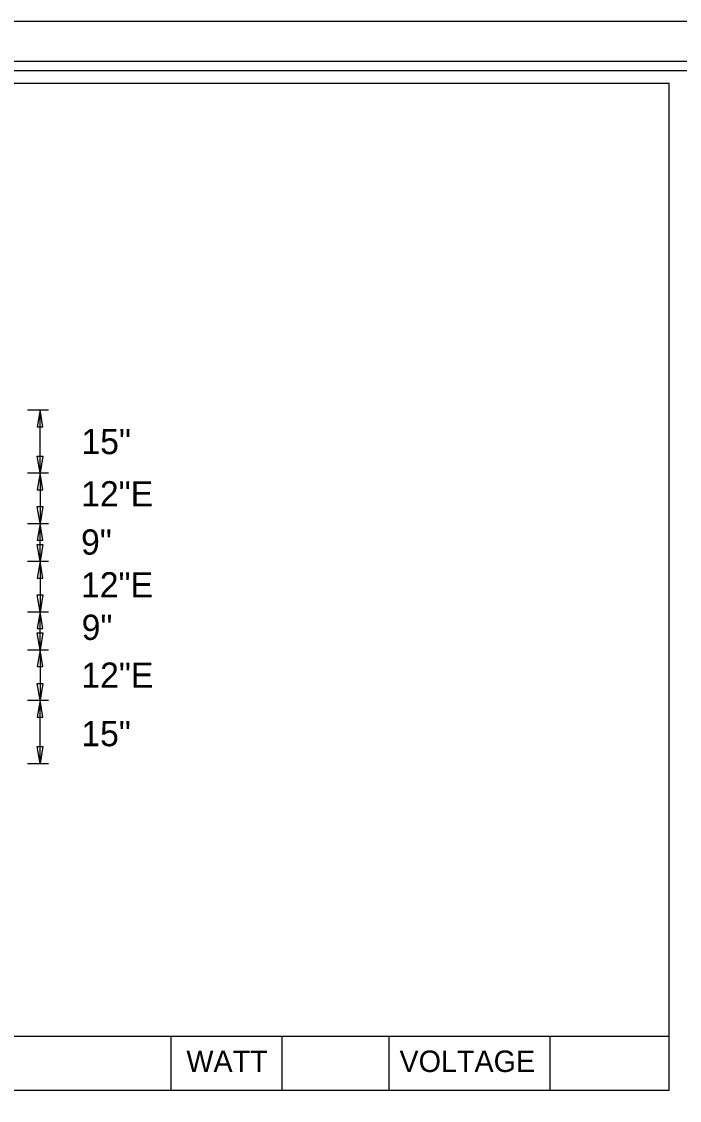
# Model space of a CAD drawing. Extents: x 121688 to 126625, y -22764 to -19972.
# Drawn here: x 125690.2 to 125846.6, y -22010.6 to -21754.2 of the extents above; entities that cross this region are included whole.
import ezdxf

# ---------------------------------------------------------------- set-up
doc = ezdxf.new("R2010")
doc.units = 0
for name, color, linetype in [('GSDims', 7, 'Continuous'), ('PlotBorder_dp', 7, 'Continuous'), ('SheetBorder_dp', 7, 'Continuous'), ('SheetLinesMisc2_dp', 7, 'Continuous'), ('TextMinor', 7, 'Continuous')]:
    doc.layers.add(name, color=color, linetype=linetype)

msp = doc.modelspace()

# ---------------------------------------------------------------- linework, layer by layer
at = {"layer": 'GSDims'}
for p, q in [((125691.61, -21846.48), (125696.61, -21846.48)), ((125691.61, -21846.48), (125691.61, -21846.48)), ((125694.61, -21861.47), (125694.61, -21846.48)), ((125691.61, -21861.47), (125696.61, -21861.47)), ((125691.61, -21861.47), (125696.61, -21861.47)), ((125694.61, -21861.47), (125694.61, -21873.47)), ((125691.61, -21873.47), (125696.61, -21873.47)), ((125691.61, -21873.47), (125696.61, -21873.47)), ((125694.61, -21882.47), (125694.61, -21873.47)), ((125691.61, -21882.47), (125696.61, -21882.47)), ((125691.61, -21882.47), (125696.61, -21882.47)), ((125694.61, -21882.47), (125694.61, -21894.47)), ((125691.61, -21894.47), (125696.61, -21894.47)), ((125691.61, -21894.47), (125696.61, -21894.47)), ((125694.61, -21903.48), (125694.61, -21894.47)), ((125691.61, -21903.48), (125696.61, -21903.48)), ((125691.61, -21903.48), (125696.61, -21903.48)), ((125694.61, -21903.48), (125694.61, -21915.48)), ((125691.61, -21915.48), (125696.61, -21915.48)), ((125691.61, -21915.48), (125696.61, -21915.48)), ((125694.61, -21930.48), (125694.61, -21915.48)), ((125691.61, -21930.48), (125696.61, -21930.48)), ((125691.61, -21930.48), (125691.61, -21930.48))]:
    msp.add_line(p, q, dxfattribs=at)
for points in [[(125694.61, -21846.48), (125693.94, -21850.48), (125695.28, -21850.48)], [(125694.61, -21861.47), (125693.94, -21857.47), (125695.28, -21857.47)], [(125694.61, -21861.47), (125693.94, -21865.47), (125695.28, -21865.47)], [(125694.61, -21873.47), (125693.94, -21869.47), (125695.28, -21869.47)], [(125694.61, -21873.47), (125693.94, -21877.47), (125695.28, -21877.47)], [(125694.61, -21882.47), (125693.94, -21878.47), (125695.28, -21878.47)], [(125694.61, -21882.47), (125693.94, -21886.47), (125695.28, -21886.47)], [(125694.61, -21894.47), (125693.94, -21890.47), (125695.28, -21890.47)], [(125694.61, -21894.47), (125693.94, -21898.47), (125695.28, -21898.47)], [(125694.61, -21903.48), (125693.94, -21899.48), (125695.28, -21899.48)], [(125694.61, -21903.48), (125693.94, -21907.48), (125695.28, -21907.48)], [(125694.61, -21915.48), (125693.94, -21911.48), (125695.28, -21911.48)], [(125694.61, -21915.48), (125693.94, -21919.48), (125695.28, -21919.48)], [(125694.61, -21930.48), (125693.94, -21926.48), (125695.28, -21926.48)]]:
    msp.add_lwpolyline(points, close=True, dxfattribs=at)
at = {"layer": 'PlotBorder_dp'}
msp.add_lwpolyline([(125072.61, -22751.63), (126625.18, -22751.63), (126625.18, -21754.22), (125072.61, -21754.22)], close=True, dxfattribs=at)
at = {"layer": 'SheetBorder_dp'}
msp.add_line((125124.37, -21763.63), (126573.42, -21763.63), dxfattribs=at)
at = {"layer": 'SheetLinesMisc2_dp'}
for p, q in [((125126.93, -21765.86), (126571.13, -21765.86)), ((125352.94, -21768.85), (125844.12, -21768.85)), ((125844.12, -22008.11), (125844.12, -21768.85)), ((125352.94, -21995.29), (125844.12, -21995.29)), ((125725.74, -21995.29), (125725.74, -22008.11)), ((125752.09, -21995.29), (125752.09, -22008.11)), ((125777.5, -21995.29), (125777.5, -22008.11)), ((125815.76, -21995.29), (125815.76, -22008.11)), ((125352.94, -22008.11), (125844.12, -22008.11))]:
    msp.add_line(p, q, dxfattribs=at)

# ---------------------------------------------------------------- texts
at = {"layer": 'GSDims'}
for s, p in [('15"', (125704.45, -21857.01)), ('12"E', (125704.38, -21869.43)), ('9"', (125704.36, -21880.89)), ('12"E', (125704.35, -21891.06)), ('9"', (125704.51, -21901.15)), ('12"E', (125704.43, -21912.52)), ('15"', (125704.42, -21926.41))]:
    msp.add_text(s, height=6, dxfattribs=at).set_placement(p)
at = {"layer": 'TextMinor'}
for s, p in [('WATT', (125729.4, -22003.82)), ('VOLTAGE', (125780.05, -22003.82))]:
    msp.add_text(s, height=5.102, dxfattribs=at).set_placement(p)

doc.saveas('drawing.dxf')
